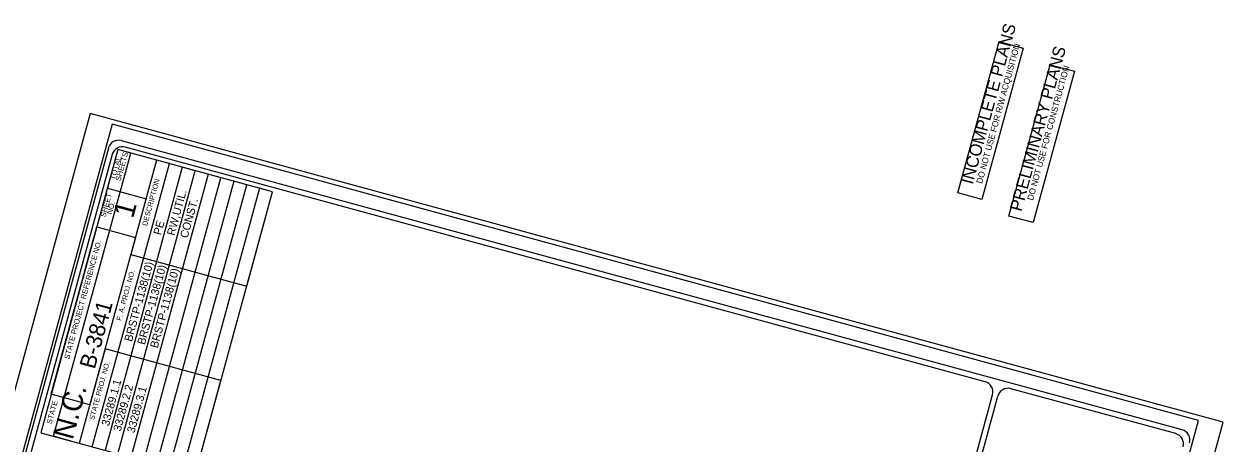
# Model space of a CAD drawing. Extents: x 2076126 to 2079903, y 925480 to 928006.
# Drawn here: x 2078780 to 2079903, y 927085 to 927478 of the extents above; entities that cross this region are included whole.
import ezdxf

# ---------------------------------------------------------------- set-up
doc = ezdxf.new("R2010")
doc.units = 0
for name, color, linetype in [('Sheet Data Field CELL', 7, 'Continuous'), ('Sheet Plot Border Inside CELL', 7, 'Continuous'), ('Sheet Plot Border Outside CELL', 7, 'Continuous'), ('Sheet Title CELL', 7, 'Continuous')]:
    doc.layers.add(name, color=color, linetype=linetype)

msp = doc.modelspace()

# ---------------------------------------------------------------- linework, layer by layer
at = {"layer": 'Sheet Plot Border Inside CELL'}
msp.add_lwpolyline([(2079441.8, 925498.6), (2079880.3, 927106.4), (2078862.4, 927384), (2078423.9, 925776.2)], close=True, dxfattribs=at)
at = {"layer": 'Sheet Plot Border Outside CELL'}
msp.add_lwpolyline([(2078841.9, 927394.2), (2078398.8, 925769.6), (2079460, 925480.1), (2079903.2, 927104.8)], close=True, dxfattribs=at)
at = {"layer": 'Sheet Title CELL'}
for p, q in [((2079313.7, 925760.5), (2079687.3, 927130.5)), ((2079651.3, 926979.4), (2079692.1, 927129.2))]:
    msp.add_line(p, q, dxfattribs=at)
for points in [[(2079677.3, 927313.4), (2079654.6, 927319.6), (2079693.3, 927461.4), (2079716, 927455.2)], [(2079725.2, 927291.8), (2079702.6, 927298), (2079741.2, 927439.8), (2079763.9, 927433.7)]]:
    msp.add_lwpolyline(points, close=True, dxfattribs=at)
for points in [[(2079864.9, 927097.6), (2078871.2, 927368.6)], [(2078859, 927361.6), (2078469.5, 925933.8)], [(2078843.8, 927081.7), (2078916.1, 927347.1), (2078904.1, 927350.3), (2078831.7, 927085), (2078807.6, 927091.6), (2078879.9, 927356.9), (2078867.9, 927360.2), (2078795.5, 927094.9), (2078940.2, 927055.4), (2078964.4, 927143.9), (2078855.8, 927173.5), (2078841.6, 927121.2), (2078805.4, 927131.1), (2078848.2, 927287.9), (2078884.3, 927278), (2078879.9, 927261.9), (2078988.5, 927232.3), (2079012.6, 927320.7), (2078867.9, 927360.2), (2078858, 927324), (2078894.2, 927314.2)], [(2079680.3, 927142.8), (2078874.7, 927362.5)], [(2078862.5, 927355.5), (2078488.8, 925985.5)], [(2078867.9, 927075.2), (2078940.2, 927340.5), (2078928.2, 927343.8), (2078855.8, 927078.5)], [(2078892, 927068.6), (2078964.4, 927333.9), (2078952.3, 927337.2), (2078879.9, 927071.9)], [(2078916.1, 927062), (2078988.5, 927327.3), (2078976.4, 927330.6), (2078904.1, 927065.3)], [(2078940.2, 927055.4), (2079012.6, 927320.7), (2079000.5, 927324), (2078928.2, 927058.7)], [(2079858.8, 927094.1), (2079704.4, 927136.2)], [(2079858.8, 927094.1), (2079704.4, 927136.2)]]:
    msp.add_lwpolyline(points, dxfattribs=at)
for centre, start, end in [((2078868.5, 927359), 74.7434, 164.7434), ((2078872.1, 927352.9), 74.7434, 164.7434), ((2079677.6, 927133.1), 344.7434, 74.7434), ((2079701.7, 927126.6), 74.7434, 164.7434), ((2079862.2, 927088), 344.7434, 74.7434), ((2079862.2, 927088), 344.7434, 74.7434), ((2079856.1, 927084.5), 344.7434, 74.7434)]:
    msp.add_arc(centre, 10, start, end, dxfattribs=at)

# ---------------------------------------------------------------- texts
at = {"layer": 'Sheet Data Field CELL'}
for s, height, p in [('RW,UTIL.  ', 7.5, (2078920.8, 927279.2)), ('CONST.', 7.5, (2078933.1, 927276.8)), ('   PE     ', 7.5, (2078905.9, 927271.6)), ('BRSTP-1138(10)', 7.5, (2078880.9, 927179.8)), ('BRSTP-1138(10)', 7.5, (2078893, 927176.9)), ('BRSTP-1138(10)', 7.5, (2078905, 927173.7)), ('B-3841    ', 15, (2078846.1, 927153.9)), ('33289.1.1 ', 7.5, (2078859.4, 927100.7)), ('33289.2.2 ', 7.5, (2078870.5, 927095.8)), ('33289.3.1 ', 7.5, (2078883.3, 927094.2))]:
    msp.add_text(s, height=height, rotation=74.7434, dxfattribs=at).set_placement(p)
at = {"layer": 'Sheet Title CELL'}
for s, height, p in [('INCOMPLETE PLANS', 11.52, (2079668.6, 927327)), ('DO NOT USE FOR R/W ACQUISITION', 5.76, (2079677.4, 927327.9)), ('PRELIMINARY PLANS', 11.52, (2079714.3, 927301.6)), ('DO NOT USE FOR CONSTRUCTION', 5.76, (2079725.1, 927312.2)), ('SHEETS', 5, (2078870.3, 927330.5)), ('TOTAL', 5, (2078865.4, 927331.5)), ('DESCRIPTION', 4.8, (2078895.1, 927288.4)), ('SHEET', 5, (2078856.2, 927296.5)), ('NO.', 5, (2078862.1, 927299.2)), ('1', 19.4, (2078881.9, 927295.1)), ('STATE PROJECT REFERENCE NO.', 5, (2078822.2, 927163.4)), ('F. A. PROJ. NO.', 4.8, (2078870.9, 927199.5)), ('STATE PROJ. NO.', 4.8, (2078845.5, 927106.6)), ('N.C.', 19.35, (2078825.3, 927087.6)), ('STATE', 5, (2078805.7, 927102.8))]:
    msp.add_text(s, height=height, rotation=74.7434, dxfattribs=at).set_placement(p)

doc.saveas('drawing.dxf')
